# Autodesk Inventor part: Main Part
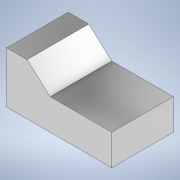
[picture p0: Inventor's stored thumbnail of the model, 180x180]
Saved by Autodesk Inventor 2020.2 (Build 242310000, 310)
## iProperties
Created: 2020-01
Part Number: Main Part
Material: Nickel-Copper Alloy 400
Document SubType Name: Modeling
Designer: thira
Density: 8.83 g/cm^3
Appearance: Chrome - Polished
Author: thira
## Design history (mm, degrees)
sketch "Sketch1"
  geometry: L1 (0, 0)-(0, 50); L2 (0, 50)-(20, 50); L3 (20, 50)-(42.361, 30); L4 (42.361, 30)-(102.361, 30); L5 (102.361, 30)-(102.361, 0); L6 (102.361, 0)-(0, 0)
  constraints: 12 end point, 2 perpendicular, 1 horizontal, 1 parallel, 1 vertical
  dimensions: "d0" = 50 distance of L1.start L1.end; "d1" = 20 distance of L1.end L2.end; "d2" = 30 distance of L2.end L3.end; "d3" = 60 distance of L3.end L4.end; "d4" = 30 distance of L4.end L5.end
extrude "Extrusion1" new body sketch "Sketch1" distance "d5" = 60; taper "d6" = 0 deg
body "Solid1"
